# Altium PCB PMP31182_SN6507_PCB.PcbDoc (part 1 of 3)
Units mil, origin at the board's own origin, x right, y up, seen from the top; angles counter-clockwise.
Board outline 4922 x 2266 mil, 4 copper layers (Top Layer, Signal Layer 1, Signal Layer 2, Bottom Layer), stack 77.9 mil thick; 174 components, 102 nets, 540 pads, 580 vias.
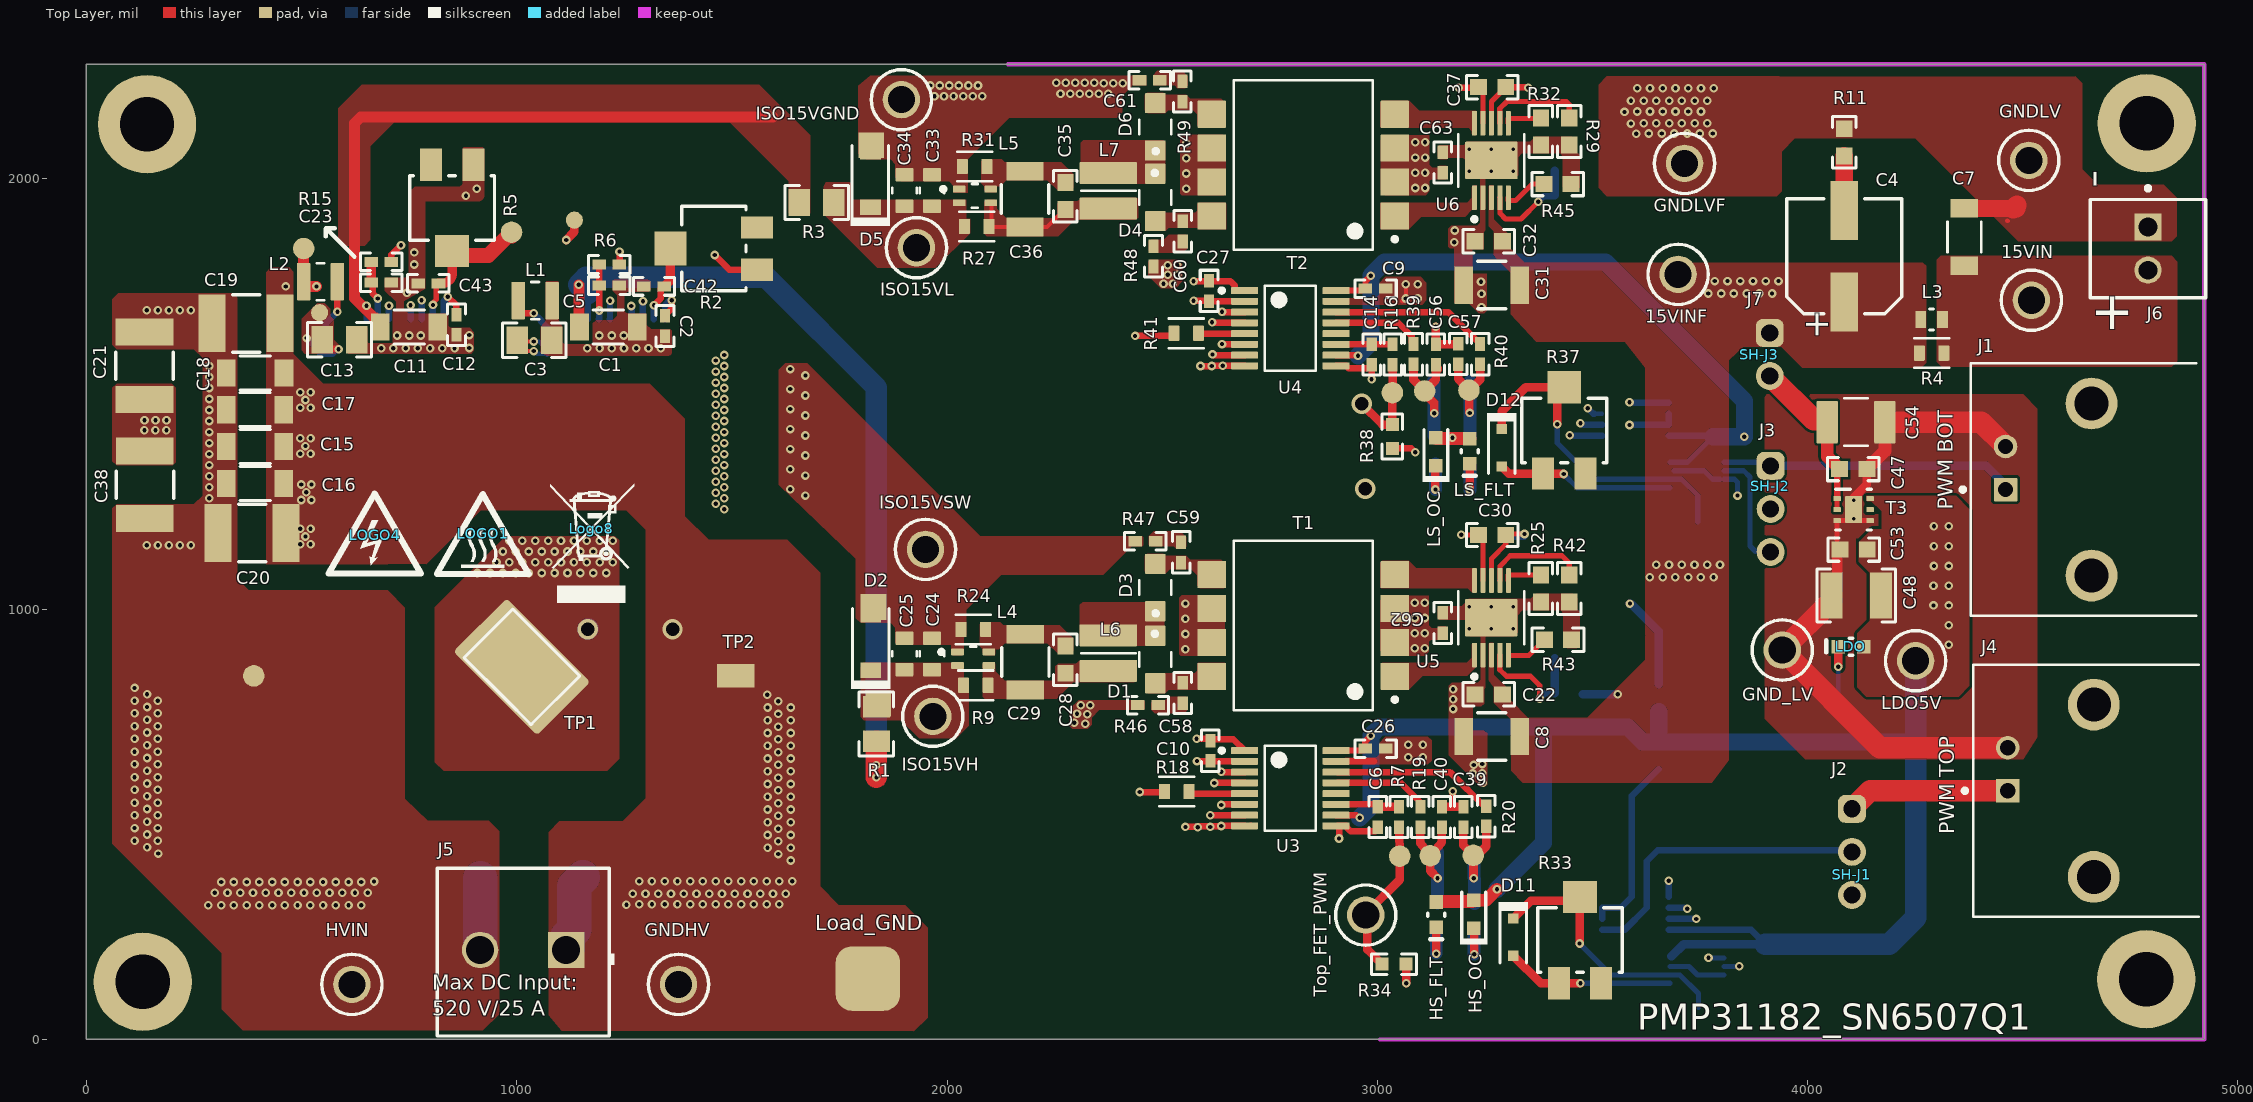
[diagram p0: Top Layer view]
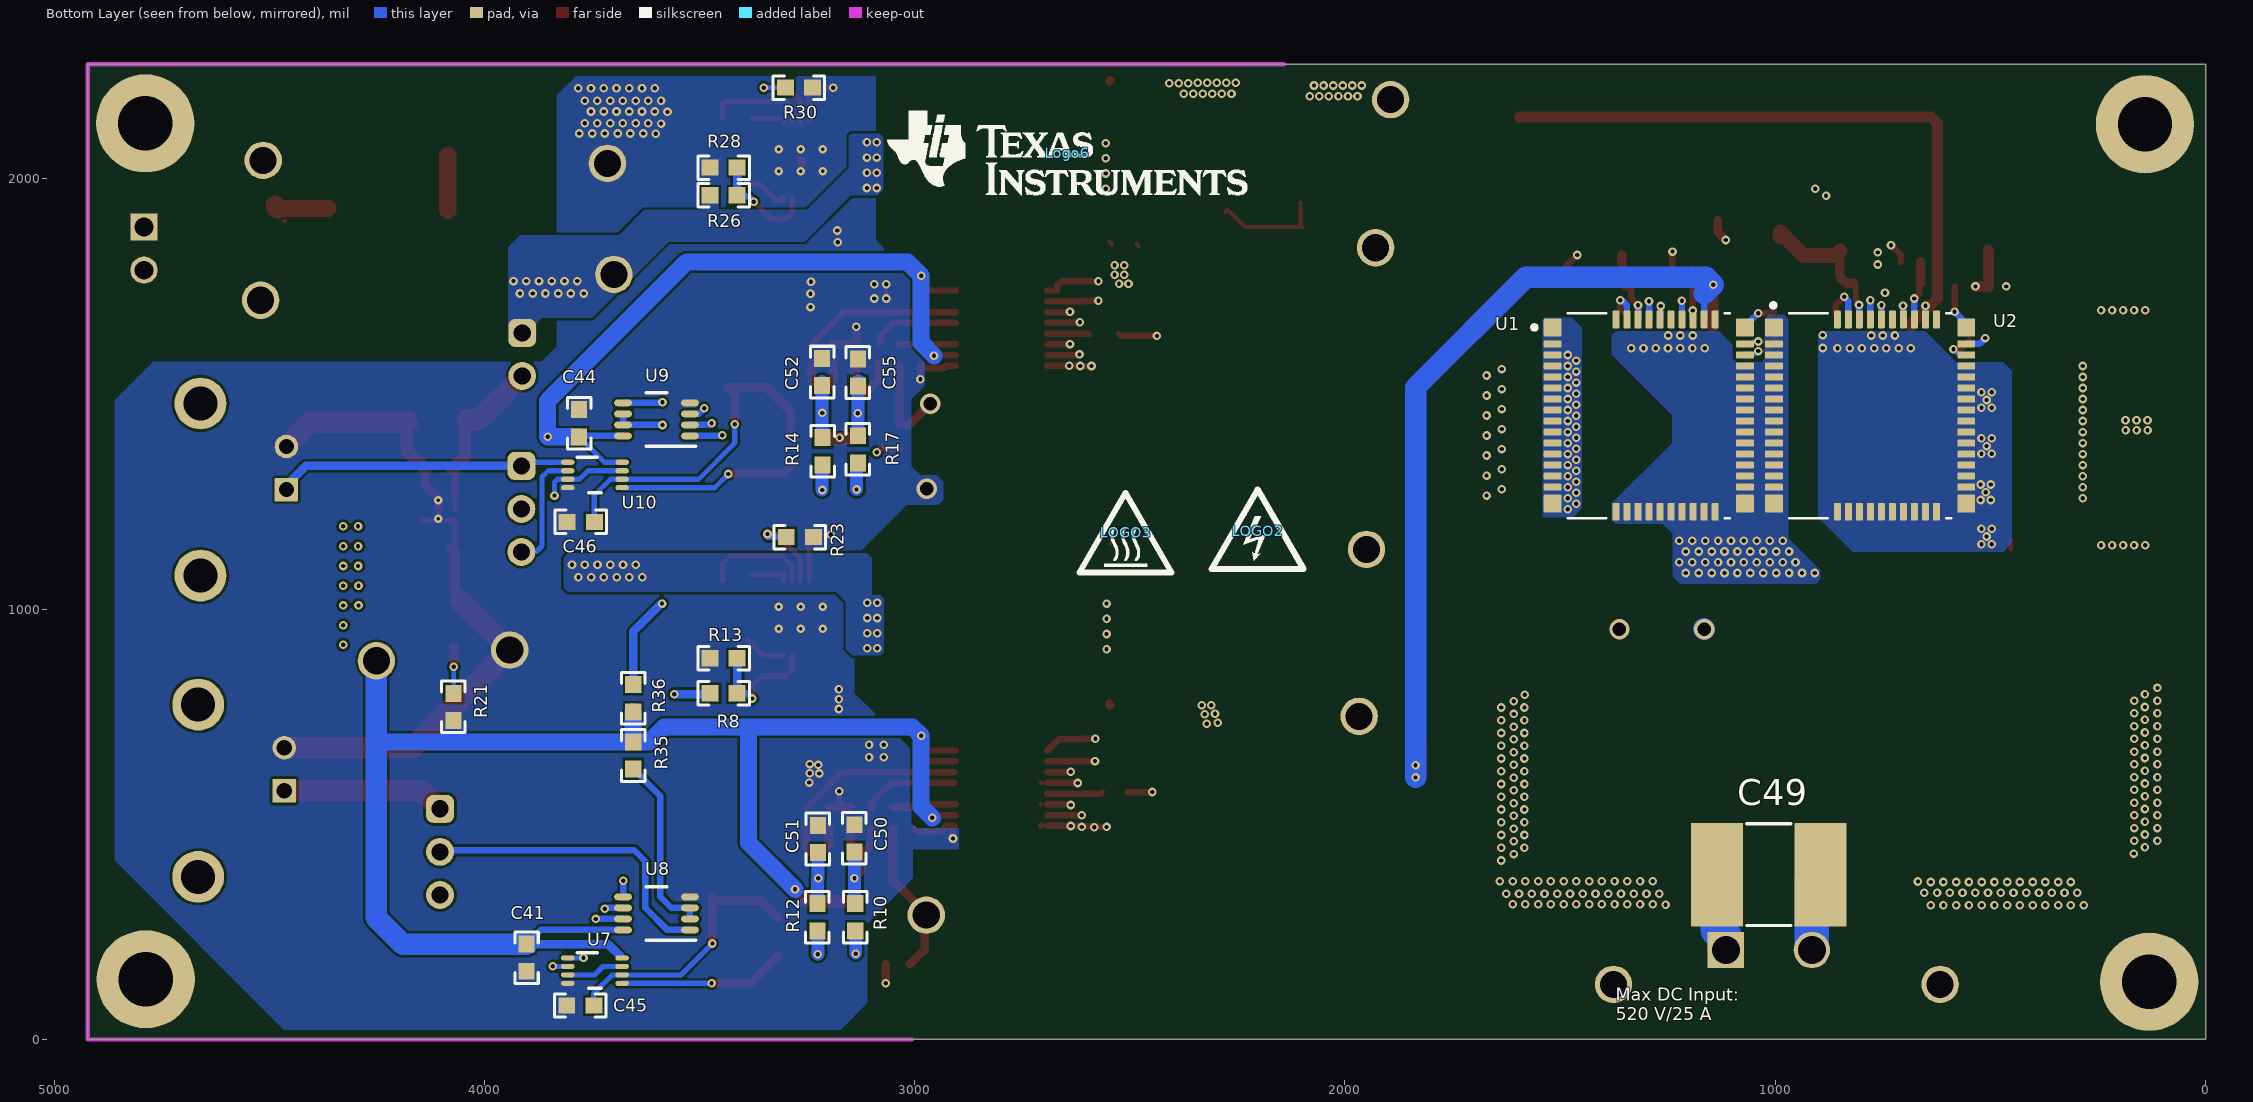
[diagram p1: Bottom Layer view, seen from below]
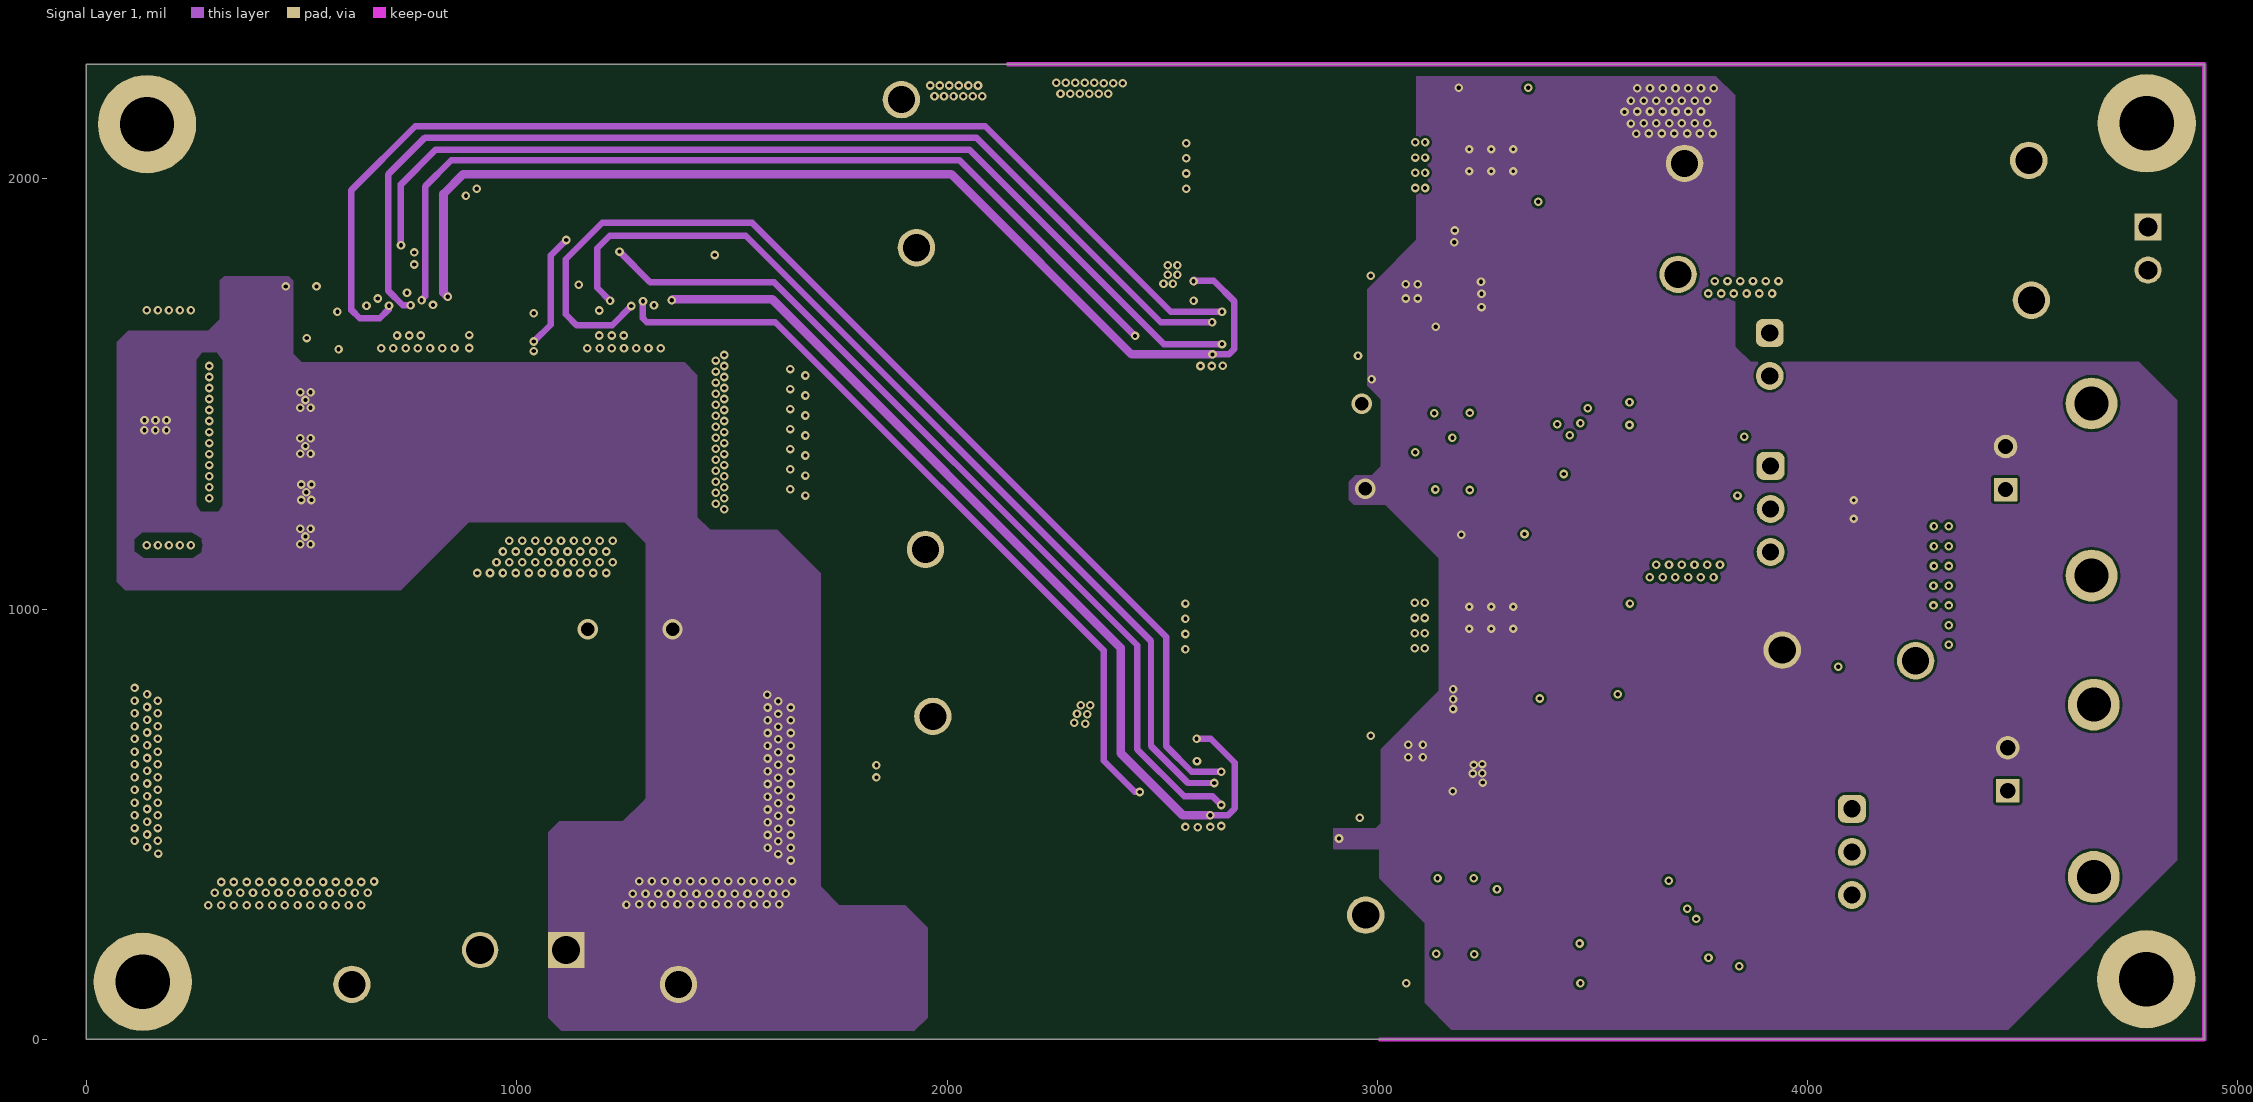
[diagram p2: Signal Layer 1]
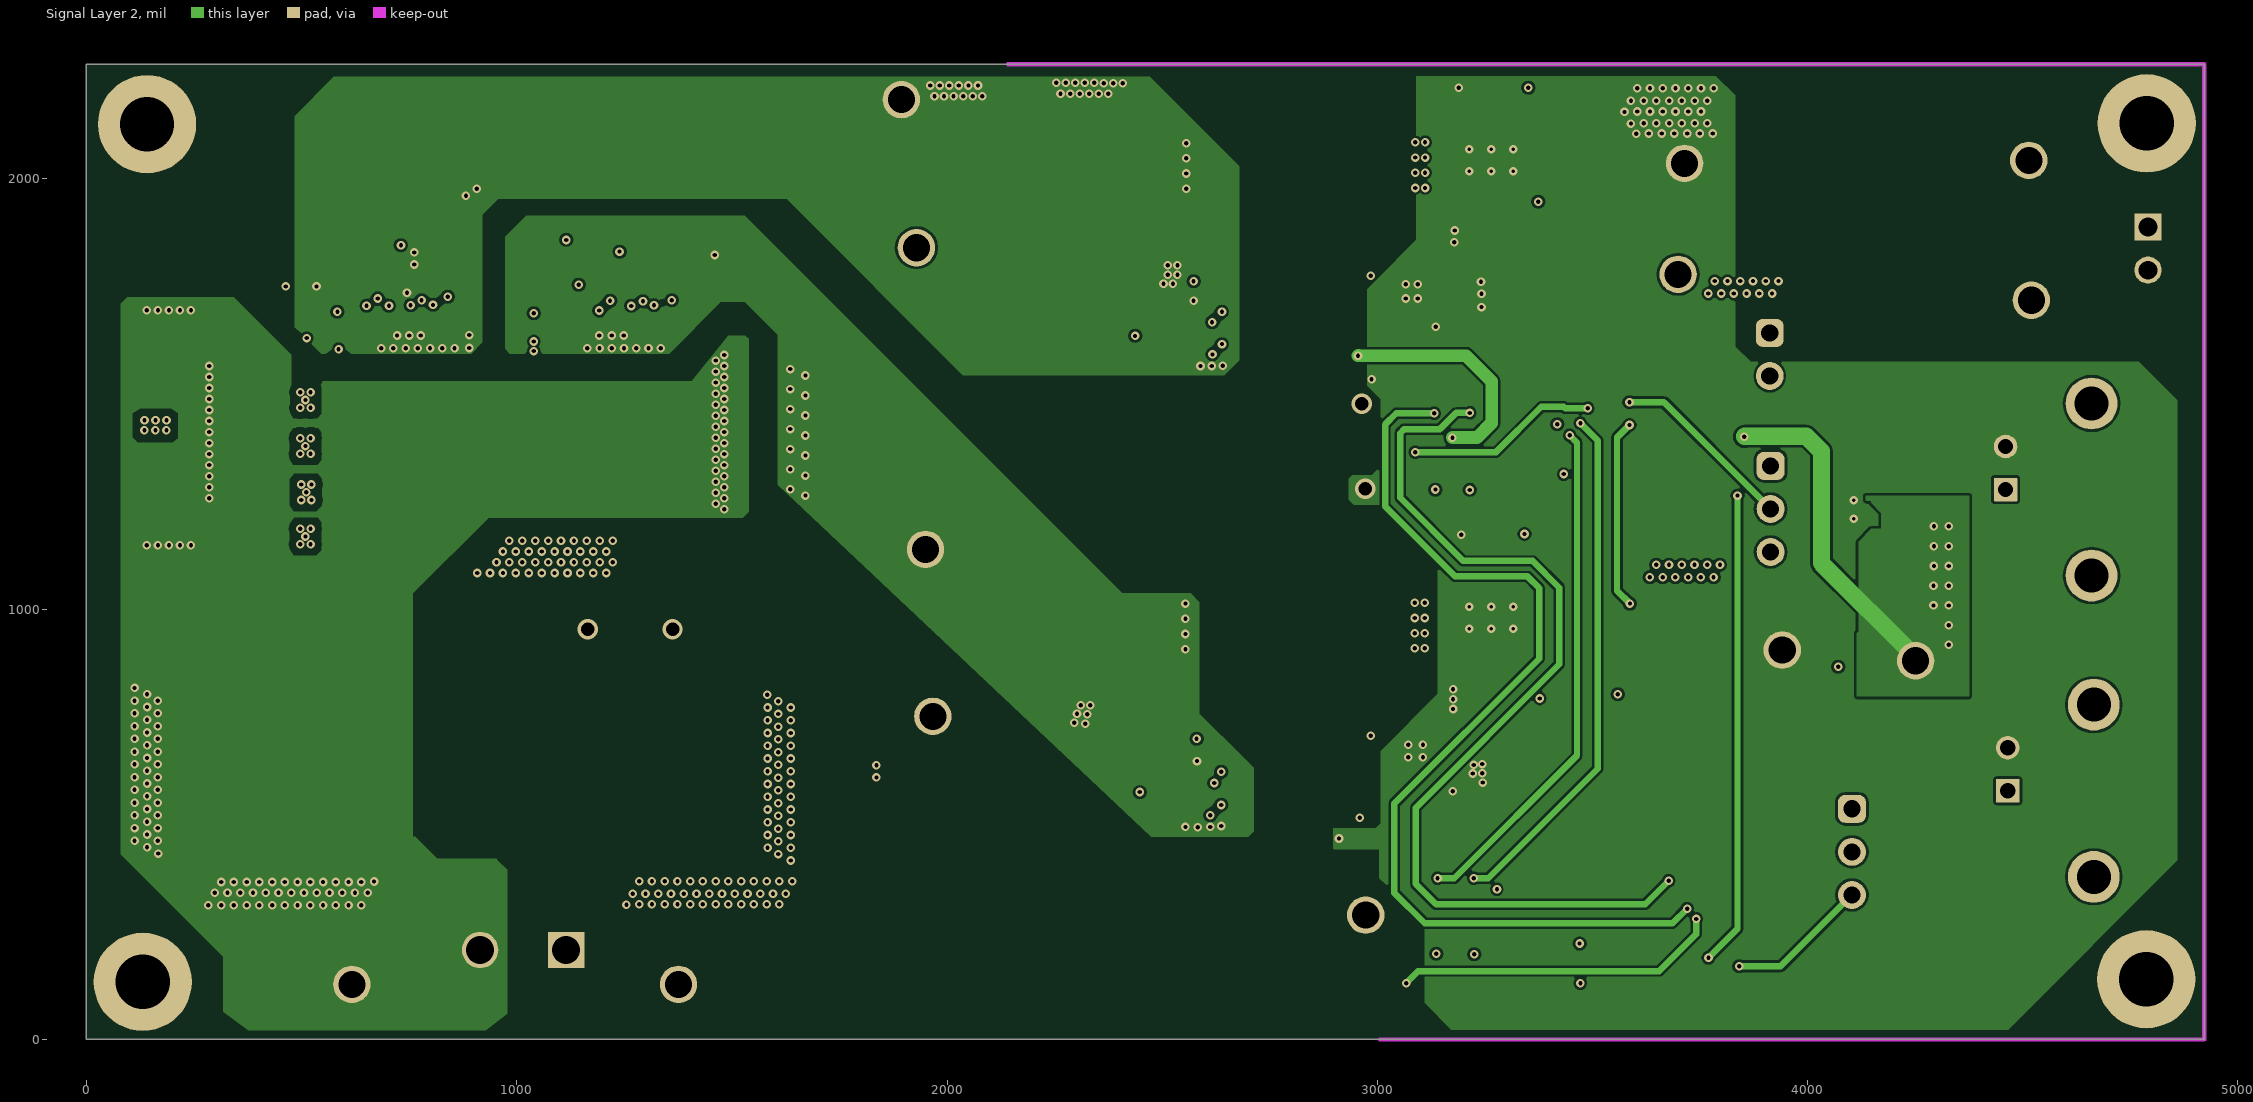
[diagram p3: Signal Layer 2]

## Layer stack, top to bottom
Top Solder: solder mask 0.4, Solder Resist, Dk 3.5
Top Layer: signal copper 2.8
Dielectric 1: prepreg 4.6, FR-4, Dk 4.2
Signal Layer 1: signal copper 2.8
Dielectric 2: core 57.5, FR-4, Dk 4.2
Signal Layer 2: signal copper 2.8
Dielectric 3: prepreg 4.6, FR-4, Dk 4.2
Bottom Layer: signal copper 2.8
Bottom Solder: solder mask 0.4, Solder Resist, Dk 3.5

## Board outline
0,2266 4922,2266 4922,0 0,0

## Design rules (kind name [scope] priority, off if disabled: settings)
AcuteAngle [All] p1: minimum=4.50000000000000E+0001 checktracksonly=FALSE
AssemblyTestPointUsage [All] p1: valid=2
BoardOutlineClearance [OnCopper] p1: gap=15 ignorepadtopadclearanceinfootprint=FALSE
Clearance "Clearance_Thermal Vias" [InNet('NC5')] p1: gap=20 ignorepadtopadclearanceinfootprint=FALSE
Clearance "Clearance_Thermal Vias_1" [InNet('NC6')] p2: gap=20 ignorepadtopadclearanceinfootprint=FALSE
Clearance Clearance_VSW_Mid1 [(OnMultiLayer Or OnMid) And InNetClass('VSWNET') vs OnMid And Not InNetClass('VSWNET')] p3: gap=16 ignorepadtopadclearanceinfootprint=TRUE
Clearance Clearance_Screw_Top [InNetClass('Screw') vs OnLayer('Top Layer') And Not InNetClass('Screw')] p4: gap=60 ignorepadtopadclearanceinfootprint=TRUE
Clearance Clearance_Screw_Bottom [InNetClass('Screw') vs OnLayer('Bottom Layer') And Not InNetClass('Screw')] p5: gap=60 ignorepadtopadclearanceinfootprint=TRUE
Clearance Clearance_Screw_Other [InNetClass('Screw') vs Not OnLayer('Top Layer')  AND Not InNetClass('Screw')] p6: gap=60 ignorepadtopadclearanceinfootprint=TRUE
Clearance Clearance_VSW_Mid2 [(OnMultiLayer Or OnMid) And Not InNetClass('VSWNET') vs OnMid And InNetClass('VSWNET')] p7: gap=16 ignorepadtopadclearanceinfootprint=TRUE
Clearance Clearance_VSW [InNetClass('VSWNET') and OnCopper vs Not InNetClass('VSWNET') and OnCopper] p8: gap=60 ignorepadtopadclearanceinfootprint=TRUE
Clearance Clearance_VHV_Mid1 [(OnMultiLayer Or OnMid) And InNetClass('VHV') vs OnMid And Not InNetClass('VHV')] p9: gap=16 ignorepadtopadclearanceinfootprint=TRUE
Clearance Clearance_VHV_Mid2 [(OnMultiLayer Or OnMid) And Not InNetClass('VHV') vs OnMid And InNetClass('VHV')] p10: gap=16 ignorepadtopadclearanceinfootprint=TRUE
Clearance Clearance_VHV [InNetClass('VHV') vs Not InNetClass('VHV')] p11: gap=60 ignorepadtopadclearanceinfootprint=FALSE
Clearance Clearance_INGND [InNetClass('INGND') and OnCopper vs Not InNetClass('INGND')  and OnCopper] p12: gap=60 ignorepadtopadclearanceinfootprint=FALSE
Clearance Clearance_Poly [All] p13: gap=6 ignorepadtopadclearanceinfootprint=FALSE
Clearance Clearance_1 [All] p14: gap=6 ignorepadtopadclearanceinfootprint=FALSE
ComponentClearance ComponentClearance_Shunt [InComponentClass('Header') vs InComponentClass('Shunt')] p1: gap=0 collisioncheckmode=3 verticalgap=0 showdistances=FALSE
ComponentClearance ComponentClearance_MountingHoles_FiducialMarks [InComponentClass('Mounting Holes') vs InComponentClass('FiducialMark')] p2 off: gap=50 collisioncheckmode=3 verticalgap=10 showdistances=FALSE
ComponentClearance ComponentClearance_Logo [InComponentClass('Logo')] p3: gap=0 collisioncheckmode=3 verticalgap=10 showdistances=FALSE
ComponentClearance ComponentClearance_ScrewToNut [(HasFootprint('NY PMS 440 0025 PH')) vs (HasFootprint('Keystone_1902C'))] p4: gap=5 collisioncheckmode=3 verticalgap=10 showdistances=FALSE
ComponentClearance ComponentClearance_MountingHoles [InComponentClass('Mounting Holes')] p5: gap=250 collisioncheckmode=3 verticalgap=100000 showdistances=FALSE
ComponentClearance ComponentClearance_SmallPassives [HasFootprint('0201*') or HasFootprint('0402*') or HasFootprint('0508') or HasFootprint('0603*') or HasFootprint('0612') or HasFootprint('0805*') or HasFootprint('0815*') or HasFootprint('0830*') or HasFootprint('1206*') or HasFootprint('1210*') or HasFootprint('1808*') or HasFootprint('1812*') or HasFootprint('1825*') or HasFootprint('2010*') or HasFootprint('2220*') or HasFootprint('2225*') or HasFootprint('2512*') or HasFootprint('2728*') or HasFootprint('3518*') vs HasFootprint('0201*') or HasFootprint('0402*') or HasFootprint('0508') or HasFootprint('0603*') or HasFootprint('0612') or HasFootprint('0805*') or HasFootprint('0815*') or HasFootprint('0830*') or HasFootprint('1206*') or HasFootprint('1210*') or HasFootprint('1808*') or HasFootprint('1812*') or HasFootprint('1825*') or HasFootprint('2010*') or HasFootprint('2220*') or HasFootprint('2225*') or HasFootprint('2512*') or HasFootprint('2728*') or HasFootprint('3518*')] p6: gap=9.84 collisioncheckmode=3 verticalgap=10 showdistances=FALSE
ComponentClearance ComponentClearance_THtoSMT [IsThruComponent vs IsSMTComponent] p7: gap=10 collisioncheckmode=3 verticalgap=30 showdistances=FALSE
ComponentClearance ComponentClearance_THtoTH [IsThruComponent vs IsThruComponent] p8: gap=74 collisioncheckmode=3 verticalgap=30 showdistances=FALSE
ComponentClearance [All] p9: gap=1 collisioncheckmode=3 verticalgap=10 showdistances=FALSE
DiffPairsRouting [All] p1: maxlimit=100 minlimit=10 mostfreqgap=10 toplayer_minwidth=15 toplayer_maxwidth=15 toplayer_prefwidth=15 midlayer1_minwidth=15 midlayer1_maxwidth=15 midlayer1_prefwidth=15 midlayer2_minwidth=15 midlayer2_maxwidth=15 midlayer2_prefwidth=15 bottomlayer_minwidth=15 bottomlayer_maxwidth=15 bottomlayer_prefwidth=15 maxuncoupledlength=1000
FabricationTestPointUsage TestPointUsage [All] p1: valid=2 allowmultiple=FALSE
FabricationTestpoint Testpoint [All] p1: side=3 testpointundercomponent=TRUE minsize=40 maxsize=100 preferedsize=60 minholesize=0 maxholesize=40 preferedholesize=32 testpointgrid=1 allowsidetop=TRUE allowsidebottom=TRUE usegrid=TRUE gridtolerance=0.01
FanoutControl Fanout_LCC [IsLCC] p1: bgadir=Out bgaviamode=Centered fanoutstyle=Auto fanoutdirection=Alternating viagrid=1 // Fanout_LCC (Default Rule)
FanoutControl Fanout_BGA [IsBGA] p2: bgadir=Out bgaviamode=Centered fanoutstyle=Auto fanoutdirection=Alternating viagrid=1 // Fanout_BGA (Default Rule)
FanoutControl Fanout_Default [All] p4: bgadir=Out bgaviamode=Centered fanoutstyle=Auto fanoutdirection=Alternating viagrid=1 // Fanout_Default (Default Rule)
FanoutControl Fanout_Small [(CompPinCount < 5)] p5: bgadir=Out bgaviamode=Centered fanoutstyle=Auto fanoutdirection=OutThenIn viagrid=1 // Fanout_Small (Default Rule)
HoleSize [All] p1: absolutevalues=TRUE maxlimit=251 minlimit=6 maxpercent=80.000 minpercent=20.000
MinimumAnnularRing MinimumAnnularRing_ThermalPadVias [IsVia and InAnyComponent] p1: minimumring=4.5
MinimumAnnularRing [IsVia] p2: minimumring=4.5
MinimumSolderMaskSliver MinimumSolderMaskSliver_Logo [InComponentClass('Logo') vs InComponentClass('Logo')] p1: minsoldermaskwidth=0.7
MinimumSolderMaskSliver [All] p2: minsoldermaskwidth=3.94
PlaneConnect [All] p1: planeconnectstyle=Relief reliefexpansion=10 reliefentries=4 reliefconductorwidth=10 reliefairgap=10
PolygonConnect [All] p1: connectstyle=Direct reliefconductorwidth=10 reliefentries=4 polygonreliefangle="90 Angle" airgapwidth=10
RoutingVias ThermalPadVias [IsVia and InAnyComponent] p1: holewidth=7.87 width=19.68 viastyle="Through Hole" minholewidth=7.87 minwidth=19.68 maxholewidth=12.99 maxwidth=23.62
RoutingVias [All] p2: holewidth=10 width=20 viastyle="Through Hole" minholewidth=6 minwidth=10 maxholewidth=40 maxwidth=65
SMDToCorner [All] p1: distance=30000
SilkToSilkClearance [All] p1: silktosilkclearance=0
SilkToSolderMaskClearance SilkscreenOverComponentPads [IsPad] p1: minsilkscreentomaskgap=5 clearancetoexposedcopper=TRUE
SolderMaskExpansion [All] p1: expansion=1.97 istentingtop=FALSE
Width [All] p1: maxlimit=1000 minlimit=6 preferedwidth=10 checkconnectedcopper=TRUE
16 further rules are at their usual default settings.

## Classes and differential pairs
component class Shunt: SH-J1 SH-J2 SH-J3
component class PMP31182_SN6507_PWM: C41 C44 C45 C46 C47 C48 C49 C50 C51 C52 C53 C54 C55 D11 D12 GND_LV GNDHV HS_FLT HS_OC HVIN J1 J2 J3 J4 J5 J7 LDO LDO5V LS_FLT LS_OC R10 R12 R14 R17 R21 R33 R34 R35 R36 R37 R38 SH-J1 SH-J2 SH-J3 T3 Top_FET_PWM U7 U8 U9 U10
component class PMP31182_SN6507_power_supply: 15VIN 15VINF 30 C4 C7 C8 C22 C24 C25 C28 C29 C30 C31 C32 C33 C34 C35 C36 C37 C58 C59 C60 C61 C62 C63 D1 D2 D3 D4 D5 D6 GNDLV GNDLVF ISO15VGND ISO15VH ISO15VL ISO15VSW J6 L3 L4 L5 L6 L7 R4 R8 R9 R11 R13 R23 R24 R25 R26 R27 R28 R29 R30 R31 R32 R42 R43 R45 R46 R47 R48 R49 T1 T2 U5 U6
component class Logo: Logo6
component class Header: J2 J3 J7
net class PGND: 5V_L FAULT_L GND_HV IN_L ISO_15V_L NC_PGND1 NC_PGND2 NC_PGND3 NetC11_2 NetC43_2 NetL2_2 NetR15_1 NetR41_2 OC_L TEMP_L VNEG_L
component class PMP31182_SN6507_Hardware: !PCB1 FID2 H3 H4 H5 H6 LOGO1 LOGO2 LOGO3 LOGO4 Logo6 Logo8
component class PMP31182_SN6507_GaN: C1 C2 C3 C5 C6 C9 C10 C11 C12 C13 C14 C15 C16 C17 C18 C19 C20 C21 C23 C26 C27 C38 C39 C40 C42 C43 C56 C57 L1 L2 R1 R2 R3 R5 R6 R7 R15 R16 R18 R19 R20 R39 R40 R41 TP1 TP2 U1 U2 U3 U4
net class VSWNET: 5V_H FAULT_H IN_H ISO_15V_H ISO_15V_H_B ISO_RET_H_B NC_SW1 NC_SW2 NC_SW3 NetC1_1 NetC42_1 NetC58_1 NetC58_2 NetC59_1 NetC59_2 NetD1_1 NetL1_2 NetR6_1 NetR18_1 OC_H SW TEMP_H VNEG_H
net class VHV: HVBUS

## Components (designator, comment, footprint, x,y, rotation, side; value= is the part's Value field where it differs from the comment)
15VIN "5005" Keystone5005 4520,1718 r180 top
15VINF "5005" Keystone5005 3699,1778 r180 top
C1 "TMK316AB7106KLHT" 1206_180 1213,1656 r0 top value=10uF
C2 "GCM155R71C224KE02D" 0402 1344.59,1658 r270 top value=0.22uF
C3 "CGA4J3X7R1E225K125AB" 0805_HV 1041,1625 r180 top value=2.2uF
C4 "HHXC250ARA470MF61G" HXB_F61 4085,1820 r90 top value=47uF
C5 "GCM1555C1H220JA16D" 0402 1215,1752 r180 top value=22pF
C6 "C1005C0G1H680J050BA" 0402 3001,517.12 r270 top value=68pF
C7 "C1206C106J3RACAUTO" 1206_180 4364,1865 r90 top value=10uF
C8 "CGA6P3X7R1H475M250AB" 1210_280 3266,704 r180 top value=4.7uF
C9 "GRT155R6YA105KE13D" 0402 2996,1744.81 r0 top value=1uF
C10 "GCM155R71H104KE02D" 0402 2612,671 r270 top value=0.1uF
C11 "TMK316AB7106KLHT" 1206_180 749.96,1656 r180 top value=10uF
C12 "GCM155R71C224KE02D" 0402 860,1661 r270 top value=0.22uF
C13 "CGA4J3X7R1E225K125AB" 0805_HV 588,1626 r180 top value=2.2uF
C14 "C1005C0G1H680J050BA" 0402 2987,1591.88 r90 top value=68pF
C15 "C1206C223KDRACTU" 1206_190 392,1378 r0 top value=0.022uF
C16 "C1206C223KDRACTU" 1206_190 392,1292 r0 top value=0.022uF
C17 "C1206C223KDRACTU" 1206_190 391.87,1463.49 r0 top value=0.022uF
C18 "C1206C223KDRACTU" 1206_190 392.15,1549.1 r0 top value=0.022uF
C19 "C1812W104KDRACTU" 1812_254 371,1664 r0 top value=0.1uF
C20 "C1812W104KDRACTU" 1812_254 385,1177 r0 top value=0.1uF
C21 "C1812W104KDRACTU" 1812_254 135,1565.74 r270 top value=0.1uF
C22 "CGA3E3X8R1H104K080AE" 0603 3259,802 r180 top value=0.1uF
C23 "GCM1555C1H220JA16D" 0402 685.1,1758.91 r180 top value=22pF
C24 "CGA4J1X7S1E106K125AC" FP-CGA4J1X7S1E106K125AC_0805-MFG 1965,896 r90 top value=10µF
C25 "CGA4J1X7S1E106K125AC" FP-CGA4J1X7S1E106K125AC_0805-MFG 1901,896 r90 top value=10µF
C26 "GRT155R6YA105KE13D" 0402 2996,676 r0 top value=1uF
C27 "GCM155R71H104KE02D" 0402 2609,1739.62 r270 top value=0.1uF
C28 "CGA3E3X8R1H104K080AE" 0603 2275,882.5 r90 top value=0.1uF
C29 "CGA6P1X7R1E106M250AC" 1210_280 2182,877 r90 top value=10uF
C30 "GCM188R71E105KA64D" 0603 3267,1172.4 r180 top value=1uF
C31 "CGA6P3X7R1H475M250AB" 1210_280 3266,1753 r180 top value=4.7uF
C32 "CGA3E3X8R1H104K080AE" 0603 3259,1855 r180 top value=0.1uF
C33 "CGA4J1X7S1E106K125AC" FP-CGA4J1X7S1E106K125AC_0805-MFG 1965,1973 r90 top value=10µF
C34 "CGA4J1X7S1E106K125AC" FP-CGA4J1X7S1E106K125AC_0805-MFG 1901,1973 r90 top value=10µF
C35 "CGA3E3X8R1H104K080AE" 0603 2275,1960 r90 top value=0.1uF
C36 "CGA6P1X7R1E106M250AC" 1210_280 2181,1953 r90 top value=10uF
C37 "GCM188R71E105KA64D" 0603 3267,2213 r180 top value=1uF
C38 "C1812W104KDRACTU" 1812_254 136,1289 r90 top value=0.1uF
C39 "GCQ1555C1H430JB01D" 0402 3200,517 r90 top value=43pF
C40 "GCQ1555C1H430JB01D" 0402 3150,517 r90 top value=43pF
C41 "CGA3E1X7R1E105K080AD" 0603 3902,190 r90 bottom value=1uF
C42 "CGA2B2C0G1H101J050BA" 0402 1319,1750 r180 top value=100pF
C43 "CGA2B2C0G1H101J050BA" 0402 794.62,1757 r0 top value=100pF
C44 "CGA3E1X7R1E105K080AD" 0603 3780,1432 r270 bottom value=1uF
C45 "GRM1885C1H390JA01D" 0603 3777,79 r0 bottom value=39pF
C46 "GRM1885C1H390JA01D" 0603 3776,1203 r0 bottom value=39pF
C47 "CGA3E3X8R1H104K080AE" 0603 4106,1325.63 r0 top value=0.1uF
C48 "GRT32ER61E226KE13L" 1210_270 4113,1031.63 r180 top value=22uF
C49 "2220Y6300105KETWS2" 2220_450 1015,383 r0 bottom value=1uF
C50 "GRM1885C1H390JA01D" 0603 3140,467.5 r90 bottom value=39pF
C51 "GRM1885C1H390JA01D" 0603 3225,466 r90 bottom value=39pF
C52 "GRM1885C1H390JA01D" 0603 3214.93,1551 r90 bottom value=39pF
C53 "CGA3E3X8R1H104K080AE" 0603 4107,1138.63 r180 top value=0.1uF
C54 "UMK325AB7106KMHP" FP-UMK325AB7106KMHP_1210-MFG 4112.43,1434.63 r180 top value=10µF
C55 "GRM1885C1H390JA01D" 0603 3131.93,1550 r90 bottom value=39pF
C56 "GCQ1555C1H430JB01D" 0402 3136,1592 r90 top value=43pF
C57 "GCQ1555C1H430JB01D" 0402 3188,1593 r90 top value=43pF
C58 "GRM1555C1H620JA01D" 0402 2548,805 r270 top value=62pF
C59 "GRM1555C1H620JA01D" 0402 2544,1132 r90 top value=62pF
C60 "GRM1555C1H620JA01D" 0402 2548,1878 r270 top value=62pF
C61 "GRM1555C1H620JA01D" 0402 2547,2203 r90 top value=62pF
C62 "C1005X6S1H104K050BB" 0402 3152,968 r90 top value=0.1uF
C63 "C1005X6S1H104K050BB" 0402 3152,2038 r90 top value=0.1uF
D1 "PMEG200G20ELRX" FP-PMEG6020ELRX_SOD123W-MFG 2484,883 r270 top
D2 "BZT52C18-7-F" SOD-123 1823,922 r90 top value=18V
D3 "PMEG200G20ELRX" FP-PMEG6020ELRX_SOD123W-MFG 2484,1050 r90 top
D4 "PMEG200G20ELRX" FP-PMEG6020ELRX_SOD123W-MFG 2484,1957 r270 top
D5 "BZT52C18-7-F" SOD-123 1822,1998 r90 top value=18V
D6 "PMEG200G20ELRX" FP-PMEG6020ELRX_SOD123W-MFG 2484,2121 r90 top
D11 "BAT42WS-7-F" SOD-323 3316,238 r270 top value=30V
D12 "BAT42WS-7-F" SOD-323 3289,1375 r270 top value=30V
GND_LV "5006" Keystone5006 3941,905 r180 top
GNDHV "5006" Keystone5006 1376,128 r180 top
GNDLV "5006" Keystone5006 4514,2043 r180 top
GNDLVF "5006" Keystone5006 3714,2036 r180 top
HS_FLT "LS L29K-G1J2-1-Z" "LS L29K_Red" 3137,290 r270 top value=Red
HS_OC "SML-E12Y8WT86" SML-E1_Yellow 3224,291 r90 top value=Yellow
HVIN "5005" Keystone5005 617,128 r0 top
ISO15VGND "5006" Keystone5006 1894,2184 r180 top
ISO15VH "5005" Keystone5005 1967,751 r180 top
ISO15VL "5005" Keystone5005 1929,1840 r180 top
ISO15VSW "5006" Keystone5006 1950,1139 r180 top
J1 "0731375003" FP-0731375003_CONN_BNC_RCPT-MFG 5074.57,1278 r90 top
J2 "TSW-103-07-G-S" TSW-103-07-G-S 4103,436 r270 top
J3 "TSW-103-07-G-S" TSW-103-07-G-S 3914,1233 r270 top
J4 "0731375003" FP-0731375003_CONN_BNC_RCPT-MFG 5079.57,578 r90 top
J5 "0395443002" Molex_0395443002 1015,208 r180 top
J6 "282834-2" TEC_282834-2 4791,1838 r270 top
J7 "TSW-102-07-G-S" TSW-102-07-G-S 3912,1592 r270 top
L1 "MPIA2510V2-4R7-R" FP-MPIA2510V2-4R7-R_1008-MFG 1043,1717 r180 top value=4.7uH
L2 "MPIA2510V2-4R7-R" FP-MPIA2510V2-4R7-R_1008-MFG 544,1761 r0 top value=4.7uH
L3 "0603PS-SRF Inductor" 0603AF 4288,1673 r180 top value=240nH
L4 "ACM2012-900-2P-T001" FP-ACM2012-900-2P-T001_SMD4-MFG 2060.92,884.75 r0 top
L5 "ACM2012-900-2P-T001" FP-ACM2012-900-2P-T001_SMD4-MFG 2065,1960.44 r0 top
L6 "74438335330" FP-74438335330_SMT2_3MM0_3MM0-MFG 2375,898 r270 top value=33uH
L7 "74438335330" FP-74438335330_SMT2_3MM0_3MM0-MFG 2375,1972 r270 top value=33uH
LDO "LS L29K-G1J2-1-Z" "LS L29K_Red" 4100.53,913 r180 top value=Red
LDO5V "5005" Keystone5005 4251,880 r180 top
LOGO1 "CAUTION HOT SURFACE" IEC_HotSurface_Small 921.25,1174.75 r0 top
LOGO2 "DANGER HIGH VOLTAGE" IEC_HighVoltage_Small 2203,1181 r180 bottom
LOGO3 "CAUTION HOT SURFACE" IEC_HotSurface_Small 2510,1178 r180 bottom
LOGO4 "DANGER HIGH VOLTAGE" IEC_HighVoltage_Small 670,1171.25 r0 top
Logo6 "Texas Instruments" TI_Stacked_Overlay_Small 2645,2060 r180 bottom
Logo8 "WEEE logo" WEEE_Minimum 1173.5,1187 r0 top
LS_FLT "LS L29K-G1J2-1-Z" "LS L29K_Red" 3215,1367 r270 top value=Red
LS_OC "SML-E12Y8WT86" SML-E1_Yellow 3136,1366 r90 top value=Yellow
R1 "CRCW08050000Z0EAHP" 0805_HV 1836,733 r270 top value=0
R2 "3224X-1-204E" TRIM_3224X 1458,1838 r180 top value=200K
R3 "CRCW08050000Z0EAHP" 0805_HV 1697,1945 r180 top value=0
R4 "ERJ-3GEY0R00V" FP-ERJ-3GEY0R00V_0603-MFG 4288,1595 r180 top
R5 "3224X-1-204E" TRIM_3224X 850,1932.39 r270 top value=200K
R6 "CRCW0402300RJNED" 0402 1215,1801 r180 top value=300
R7 "CRCW040249R9FKED" 0402 3050.5,517.12 r90 top value=49.9
R8 "RT0603BRD076K81L" 0603 3444,804.55 r0 bottom value=6.81k
R9 "ERJ-3GEY0R00V" FP-ERJ-3GEY0R00V_0603-MFG 2067,823 r180 top
R10 "CRCW06033K30JNEA" 0603 3138,284 r270 bottom value=3.3k
R11 "ERJ-3RQFR33V" 0603 4085,2085 r270 top value=0.33
R12 "CRCW06033K30JNEA" 0603 3226,284 r270 bottom value=3.3k
R13 "RT0603BRD071KL" 0603 3444,886 r180 bottom value=1.00k
R14 "CRCW06033K30JNEA" 0603 3214.07,1367 r270 bottom value=3.3k
R15 "CRCW0402300RJNED" 0402 685.1,1807 r180 top value=300
R16 "CRCW040249R9FKED" 0402 3035.5,1591.88 r90 top value=49.9
R17 "CRCW06033K30JNEA" 0603 3132,1371.5 r270 bottom value=3.3k
R18 "ERJ-3GEY0R00V" FP-ERJ-3GEY0R00V_0603-MFG 2534,576 r180 top
R19 "CRCW0402300RJNED" 0402 3100,517 r270 top value=300
R20 "CRCW0402300RJNED" 0402 3253,518.62 r270 top value=300
R21 "CRCW06033K30JNEA" 0603 4072,773 r90 bottom value=3.3k
R23 "RT0603BRD0750K5L" 0603 3267,1167.4 r0 bottom value=50.5k
R24 "ERJ-3GEY0R00V" FP-ERJ-3GEY0R00V_0603-MFG 2061,953 r180 top
R25 "" 0603 3380,1048 r90 top value=1.00k
R26 "RT0603BRD076K81L" 0603 3444,1962 r0 bottom value=6.81k
R27 "ERJ-3GEY0R00V" FP-ERJ-3GEY0R00V_0603-MFG 2069,1889.44 r180 top
R28 "RT0603BRD071KL" 0603 3444,2026 r180 bottom value=1.00k
R29 "RC0603FR-0721KL" 0603 3446,2110 r90 top value=21.0k
R30 "RT0603BRD0750K5L" 0603 3269,2212 r0 bottom value=50.5k
R31 "ERJ-3GEY0R00V" FP-ERJ-3GEY0R00V_0603-MFG 2064,2028.44 r180 top
R32 "" 0603 3380,2110 r90 top value=1.00k
R33 "3224X-1-502E" TRIM_3224X 3471,231 r90 top value=5K
R34 "CRCW06030000Z0EA" 0603_HV 3039,175 r180 top value=0
R35 "CRCW0603100KJNEAC" 0603 3654,660 r270 bottom value=100k
R36 "CRCW0603100KJNEAC" 0603 3654,793 r270 bottom value=100k
R37 "3224X-1-502E" TRIM_3224X 3434.5,1415.5 r90 top value=5K
R38 "CRCW06030000Z0EA" 0603_HV 3035,1401 r90 top value=0
R39 "CRCW0402300RJNED" 0402 3084,1592.62 r270 top value=300
R40 "CRCW0402300RJNED" 0402 3239,1592.62 r270 top value=300
R41 "ERJ-3GEY0R00V" FP-ERJ-3GEY0R00V_0603-MFG 2556,1641 r180 top
R42 "RC0603FR-0721KL" 0603 3446,1048 r90 top value=21.0k
R43 "RT0603BRD07106KL" 0603 3420,929 r180 top value=106k
R45 "RT0603BRD07106KL" 0603 3419,1988 r180 top value=106k
R46 "RMCF0402JT100R" 0402 2467,777 r0 top value=100
R47 "RMCF0402JT100R" 0402 2461,1158 r0 top value=100
R48 "RMCF0402JT100R" 0402 2480,1820 r90 top value=100
R49 "RMCF0402JT100R" 0402 2471,2229 r0 top value=100
SH-J1 "SNT-100-BK-G" SNT-100-BK-G 4103,383 r270 top value=1x2
SH-J2 "SNT-100-BK-G" SNT-100-BK-G 3913,1286 r270 top value=1x2
SH-J3 "SNT-100-BK-G" SNT-100-BK-G 3888,1591 r90 top value=1x2
T1 "ZD2113-AE" FP-TX1-ZB1459-BED_SMT8_8MM1_10MM0-MFG 2828,962 r180 top
T2 "ZD2113-AE" FP-TX1-ZB1459-BED_SMT8_8MM1_10MM0-MFG 2828,2032 r180 top
T3 "TPS7B8150QDRVRQ1" DRV0006A 4107,1231.35 r0 top
Top_FET_PWM "5007" Keystone5007 2973,289 r90 top
TP1 "5016" Testpoint_Keystone_Compact 1012,866 r135 top
TP2 "S2751-46R" Harwin_S2751-46R 1509,845 r180 top
U1 "LMG3525R030Q" RQS0052A-MFG 1294,1449.98 r180 bottom
U2 "LMG3525R030Q" RQS0052A-MFG 779.58,1449.98 r180 bottom
U3 "ISO7741FQDBQRQ1" DBQ0016A-MFG 2797.78,584 r0 top
U4 "ISO7741FQDBQRQ1" DBQ0016A-MFG 2797.78,1653 r0 top
U5 "SN6507DGQR" DGQ0010D-C01-MFG 3265,980 r90 top
U6 "SN6507DGQR" DGQ0010D-C01-MFG 3265,2043 r90 top
U7 "SN74LVC3G14DCUTG4" DCU0008A_N 3743.01,160 r180 bottom
U8 "SN74LVC2G08IDCTRQ1" DCT0008A_N 3600,293 r0 bottom
U9 "SN74LVC2G08IDCTRQ1" DCT0008A_N 3600,1441 r0 bottom
U10 "SN74LVC3G14DCUTG4" DCU0008A_N 3743.01,1311.84 r180 bottom

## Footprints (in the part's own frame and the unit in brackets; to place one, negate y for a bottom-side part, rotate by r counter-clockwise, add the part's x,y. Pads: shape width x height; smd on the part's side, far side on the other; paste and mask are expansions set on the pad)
0402 [mm] "0402 from SM-752 data"
  rect 0.8x0.6 smd: 1(-0.6,0) 2(0.6,0)
  silkscreen extent -1.22,-0.52 1.22,0.52, body extent -0.55,-0.3 0.55,0.3, height 0.6
0603 [mm] "0603 from SM-752 data"
  rect 1x0.95 smd: 1(-0.8,0) 2(0.8,0)
  silkscreen extent -1.52,-0.69 1.52,0.69, body extent -0.87,-0.47 0.87,0.47, height 1
0603_HV [mil] "Ernesto recommended land pattern.  26 mil between pads."
  rect 30x30 smd: 1(-28,0) 2(28,0)
  silkscreen extent -52,-24 52,24, body extent -34,-19 34,19, height 39
0603AF [mm] "COILCRAFT"
  rect 0.64x1.02 smd: 1(-0.64,0) 2(0.64,0)
  silkscreen extent -0.13,-0.63 0.13,0.63, body extent -0.92,-0.56 0.92,0.56, height 0.9
0805_HV [mil] "0805 with 30mil clearance between pads"
  rect 50x63 smd: 1(-40,0) 2(40,0)
  silkscreen extent -74,-40 74,40, body extent -43,-29 43,29, height 57
1206_180 [mm] "1206_180"
  rect 1.1x1.6 smd: 1(-1.7,0) 2(1.7,0)
  silkscreen extent -0.9,-1 0.9,1, body extent -1.75,-0.95 1.75,0.95, height 1.8
1206_190 [mm] "1206_190"
  rect 1.1x1.6 smd: 1(-1.7,0) 2(1.7,0)
  silkscreen extent -0.9,-1 0.9,1, body extent -1.75,-0.95 1.75,0.95, height 1.9
1210_270 [mm] "1210"
  rect 1.3x2.7 smd: 1(-1.45,0) 2(1.45,0)
  silkscreen extent -2.32,-1.57 2.32,1.57, body extent -1.7,-1.35 1.7,1.35, height 2.7
1210_280 [mm] "SMD, 2-Leads, Body 3.6x2.8mm, Height 2.8mm"
  rect 1.1x2.2 smd: 1(-1.65,0) 2(1.65,0)
  silkscreen extent -0.84,-1.4 0.84,1.4, body extent -1.8,-1.4 1.8,1.4, height 2.8
1812_254 [mm] "SMD, 2-Leads, Body 4.8x3.4mm"
  rect 1.6x3.4 smd: 1(-2,0) 2(2,0)
  silkscreen extent -0.8,-1.7 0.8,1.7, body extent -2.4,-1.7 2.4,1.7, height 2.54
2220_450 [mm] "Laird recommended land pattern"
  rrect3% 3.07x6.1 smd: 1(-3.06,0) 2(3.06,0)
  silkscreen extent -1.3,-3 1.3,3, body extent -2.8,-2.54 2.79,2.54, height 4.5
DBQ0016A-MFG [mm]
  rrect24% 1.6x0.41 smd paste+0 mask+0: 1(-2.7,2.222) 2(-2.7,1.587) 3(-2.7,0.953) 4(-2.7,0.318) 5(-2.7,-0.318) 6(-2.7,-0.953) 7(-2.7,-1.588) 8(-2.7,-2.223) 9(2.7,-2.223) 10(2.7,-1.588) 11(2.7,-0.953) 12(2.7,-0.318) 13(2.7,0.318) 14(2.7,0.953) 15(2.7,1.587) 16(2.7,2.222)
  silkscreen extent -4.17,-2.5 1.5,2.5, body extent -3.6,-2.75 3.6,2.75, height 0.25
DCT0008A_N [mm] "TSOP, 8-Leads, Body 3x2.8mm, Pitch 0.65mm, IPC Medium Density"
  oval 1.05x0.4 smd: 1(-1.975,0.975) 2(-1.975,0.325) 3(-1.975,-0.325) 4(-1.975,-0.975) 5(1.975,-0.975) 6(1.975,-0.325) 7(1.975,0.325) 8(1.975,0.975)
  silkscreen extent -2.32,-1.57 0.6,1.58, body extent -2.01,-1.47 2.01,1.48, height 1.3
DCU0008A_N [mm] "TSSOP, 8-Leads, Body 2x2.3mm, Pitch 0.5mm, IPC Medium Density"
  oval 0.8x0.3 smd: 1(-1.6,0.75) 2(-1.6,0.25) 3(-1.6,-0.25) 4(-1.6,-0.75) 5(1.6,-0.75) 6(1.6,-0.25) 7(1.6,0.25) 8(1.6,0.75)
  silkscreen extent -1.05,-1.05 0.38,1.05, body extent -1.56,-1 1.56,1, height 0.9
DGQ0010D-C01-MFG [mm]
  rrect33% 1.45x0.3 smd paste+0 mask+0: 1(-2.2,1) 2(-2.2,0.5) 3(-2.2,0) 4(-2.2,-0.5) 5(-2.2,-1) 6(2.2,-1) 7(2.2,-0.5) 8(2.2,0) 9(2.2,0.5) 10(2.2,1)
  rrect5% 2.2x3.1 smd paste-1000 mask-1000: 11(0,0)
  silkscreen extent -3.6,-1.95 1.55,1.95, body extent -3.03,-1.8 3.03,1.8, height 0.25
DRV0006A [mm] "SON, 6-Leads, Body 2x2mm, Pitch 0.65mm, Thermal Pad 1.6x1mm, TI Recommended"
  rrect33% 0.45x0.3 smd: 1(-0.975,0.65) 2(-0.975,0) 3(-0.975,-0.65) 4(0.975,-0.65) 5(0.975,0) 6(0.975,0.65)
  rrect14% 1x0.7 on Top Paste: 7(0,-0.45) 7(0,0.45)
  rrect10% 1x1.6 smd paste-0.5: 7(0,0)
  silkscreen extent -1.05,-1.2 1.05,1.2, body extent -1.05,-1.05 1.05,1.05, height 0.81
FP-0731375003_CONN_BNC_RCPT-MFG [mm]
  rrect7% 1.39x1.39 hole 0.89 paste-1000 mask+0: 1(0,15.61)
  round 1.39 hole 0.89 paste-1000 mask+0: 2(2.54,15.61)
  round 3.06 hole 2.01 paste-1000 mask+0: 3(-5.08,10.53) 4(5.08,10.53)
  silkscreen extent -7.44,4.35 7.44,18.26, body extent -7.54,-17.75 7.54,17.75, height 0.25
FP-74438335330_SMT2_3MM0_3MM0-MFG [mm]
  rrect8% 1.3x3.4 smd paste+0 mask+0: 1(-1.05,0) 2(1.05,0)
  silkscreen extent 0,-1.6 0,1.6, body extent -1.8,-1.8 1.8,1.8, height 0.25
FP-ACM2012-900-2P-T001_SMD4-MFG [mm]
  rrect25% 0.75x0.4 smd paste+0 mask+0: 1(-0.925,0.4) 2(-0.925,-0.4) 3(0.925,-0.4) 4(0.925,0.4)
  silkscreen extent -2,-0.7 0.18,0.7, body extent -1.4,-0.8 1.4,0.8, height 0.25
FP-CGA4J1X7S1E106K125AC_0805-MFG [mm]
  rrect13% 0.8x1.05 smd paste+0 mask+0: 1(-0.925,0) 2(0.925,0)
  silkscreen extent -0.15,-0.72 0.15,0.72, body extent -1.43,-0.82 1.43,0.82, height 0.25
FP-ERJ-3GEY0R00V_0603-MFG [mm]
  rrect15% 0.65x0.9 smd paste+0 mask+0: 1(-0.725,0) 2(0.725,0)
  silkscreen extent -1.03,-0.87 1.03,0.87, body extent -1.15,-0.58 1.15,0.58, height 0.25
FP-MPIA2510V2-4R7-R_1008-MFG [mm]
  rrect13% 0.8x2.2 smd paste+0 mask+0: 1(-1,0) 2(1,0)
  silkscreen extent -0.23,-1.1 0.23,1.1, body extent -1.5,-1.2 1.5,1.2, height 0.25
FP-PMEG6020ELRX_SOD123W-MFG [mm]
  rrect8% 1.2x1.2 smd paste-1000 mask+0: 1(-1.4,0) 2(1.4,0)
  silkscreen extent -2.85,-0.95 0.43,0.95, body extent -2.2,-1.05 2.2,1.05, height 0.25
FP-TX1-ZB1459-BED_SMT8_8MM1_10MM0-MFG [mm]
  rrect6% 1.7x1.6 smd paste+0 mask+0: 1(-5.4,3) 2(-5.4,1) 3(-5.4,-1) 4(-5.4,-3) 5(5.4,-3) 6(5.4,-1) 7(5.4,1) 8(5.4,3)
  silkscreen extent -5.53,-5 4.1,5, body extent -6.35,-5.1 6.35,5.1, height 0.25
FP-UMK325AB7106KMHP_1210-MFG [mm]
  rrect8% 1.25x2.5 smd paste+0 mask+0: 1(-1.7,0) 2(1.7,0)
  silkscreen extent -0.7,-1.4 0.7,1.4, body extent -2.42,-1.5 2.42,1.5, height 0.25
Harwin_S2751-46R [mm] "Test Point, SMT"
  rect 2.2x1.4 smd: 1(0,0)
  body extent -1,-0.6 1,0.6, height 1.4
HXB_F61 [mm] "SMD, 2-Leads, Dia 6.3mm"
  rect 3.5x1.6 smd: 1(-2.7,0) 2(2.7,0)
  silkscreen extent -3.4,-3.4 3.4,3.4, body extent -3.4,-3.4 3.4,3.4, height 6.11
IEC_HighVoltage_Small [mil]
  silkscreen extent -107,-88 107,97
IEC_HotSurface_Small [mil]
  silkscreen extent -107,-93 107,92
Keystone5005 [mil] "Keystone Compact loops"
  round 87 hole 63: 1(0,0)
  silkscreen extent -70,-70 70,70, body extent -63,-63 62,63, height 225
Keystone5006 [mil] "Keystone Compact loops"
  round 87 hole 63: 1(0,0)
  silkscreen extent -70,-70 70,70, body extent -63,-63 62,63, height 225
Keystone5007 [mil] "Keystone Compact loops"
  round 87 hole 63: 1(0,0)
  silkscreen extent -70,-70 70,70, body extent -63,-63 62,63, height 225
"LS L29K_Red" [mm] "SMD, 2-Leads, Body 1.3x0.8mm"
  rect 0.8x0.8 smd paste-0.4: 1(-0.75,0) 2(0.75,0)
  silkscreen extent -0.1,-0.5 1.45,0.5, body extent -0.9,-0.45 0.9,0.45, height 0.67
Molex_0395443002 [mm] "Terminal Block, 5.08mm, 2x1, TH"
  rect 2.15x2.15 hole 1.65: 1(-2.54,0)
  round 2.15 hole 1.65: 2(2.54,0)
  silkscreen extent -5.4,-4.83 5.08,5.08, body extent -5.08,-4.83 5.08,5.08, height 14.48
RQS0052A-MFG [mm]
  rrect10% 1.05x1.05 smd paste+0 mask+0: 1(-5.675,5.2) 16(-5.675,-5.2) 27(5.675,-5.2) 42(5.675,5.2)
  rrect25% 1.05x0.4 smd paste+0 mask+0: 2(-5.675,4.225) 3(-5.675,3.575) 4(-5.675,2.925) 5(-5.675,2.275) 6(-5.675,1.625) 7(-5.675,0.975) 8(-5.675,0.325) 9(-5.675,-0.325) 10(-5.675,-0.975) 11(-5.675,-1.625) 12(-5.675,-2.275) 13(-5.675,-2.925) 14(-5.675,-3.575) 15(-5.675,-4.225) 28(5.675,-4.225) 29(5.675,-3.575) 30(5.675,-2.925) 31(5.675,-2.275) 32(5.675,-1.625) 33(5.675,-0.975) 34(5.675,-0.325) 35(5.675,0.325) 36(5.675,0.975) 37(5.675,1.625) 38(5.675,2.275) 39(5.675,2.925) 40(5.675,3.575) 41(5.675,4.225)
  rrect25% 0.4x1.05 smd paste+0 mask+0: 17(-1.935,-5.675) 18(-1.285,-5.675) 19(-0.635,-5.675) 20(0.015,-5.675) 21(0.665,-5.675) 22(1.315,-5.675) 23(1.965,-5.675) 24(2.615,-5.675) 25(3.265,-5.675) 26(3.915,-5.675) 43(3.915,5.675) 44(3.265,5.675) 45(2.615,5.675) 46(1.965,5.675) 47(1.315,5.675) 48(0.665,5.675) 49(0.015,5.675) 50(-0.635,5.675) 51(-1.285,5.675) 52(-1.935,5.675)
  silkscreen extent -6.88,-6.05 4.77,6.05, body extent -6,-6 6,6, height 1
SML-E1_Yellow [mm] "SMD, 2-Leads, Body 1.6x0.8mm"
  rect 0.8x0.8 smd: 1(0.825,0) 2(-0.825,0)
  silkscreen extent -1.8,-0.8 1.3,0.8, body extent -0.85,-0.45 0.85,0.45, height 0.46
SNT-100-BK-G [mil] "Samtec STEP model"
  round 1 on Mech3: 0(0,0)
  body extent -100,-50 100,50, height 344
SOD-123 [mm] "On Semi recommended land pattern"
  rect 0.915x1.22 smd: 1(-1.637,0) 2(1.637,0)
  silkscreen extent -2.74,-1.17 2.03,1.17, body extent -1.93,-0.9 1.93,0.9, height 1.35
SOD-323 [mm] "NXP recommended land pattern"
  rect 0.6x0.6 smd paste-0.05: 1(-1.1,0) 2(1.1,0)
  silkscreen extent -2.06,-0.87 1.53,0.86, body extent -1.3,-0.67 1.3,0.68, height 1.1
TEC_282834-2 [mm] "TEC"
  rect 1.6x1.6 hole 1.1: 1(-1.27,0)
  round 1.6 hole 1.1: 2(1.27,0)
  silkscreen extent -3.66,-3.4 2.9,3.4, body extent -2.77,-3.25 2.77,3.25, height 10.01
Testpoint_Keystone_Compact [mil] "Compact SMT test point"
  rrect10% 275x175 smd: 1(0,0)
  silkscreen extent -110,-80 110,80, body extent -75,-56 75,56, height 91
TI_Stacked_Overlay_Small [mil]
  silkscreen extent -418,-98 418,98
TRIM_3224X [mm] "Bourns"
  rect 1.9x1.3 smd: 1(-2.55,1.25) 3(-2.55,-1.25)
  rect 1.9x2 smd: 2(2.55,0)
  silkscreen extent -1.9,-2.5 1.9,2.5, body extent -1.8,-2.4 1.8,2.4, height 5.31
TSW-102-07-G-S [mm] "Samtec 100mil, 1x2, 230 mil above insulator"
  rrect50% 1.65x1.65 hole 1.016: 1(-1.27,0)
  round 1.65 hole 1.016: 2(1.27,0)
  body extent -2.54,-1.27 2.54,1.27, height 8.38
TSW-103-07-G-S [mm] "Samtec 100mil, 1x3, 230 mil above insulator"
  rrect50% 1.65x1.65 hole 1.016: 1(-2.54,0)
  round 1.65 hole 1.016: 2(0,0) 3(2.54,0)
  body extent -3.81,-1.27 3.81,1.27, height 8.38
WEEE_Minimum [mil] "WEEElie bin"
  silkscreen extent -95,-172 99,104

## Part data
15VIN 15VINF: library part CMP-0055142-2, "Test Point, Compact, Red, TH", Color=Red, Manufacturer="Keystone Electronics", Supplier Part Number 1=36-5005-ND
C1 C11: library part CMP-0750154-1, "CAP, CERM, 10 µF, 25 V,+/- 10%, X7R, AEC-Q200 Grade 1, 1206", Cap_Case=1206, Manufacturer="Taiyo Yuden", TempCo=X7R, Tolerance_%=10%, Value2=25V, ValueDisplayed=10µF
C2 C12: library part CMP-0078265-1, "CAP, CERM, 0.22 µF, 16 V,+/- 10%, X7R, AEC-Q200 Grade 1, 0402", Cap_Case=0402, Manufacturer=MuRata, Supplier Part Number 1=490-10671-1-ND, TempCo=X7R, Tolerance_%=10%, Value2=16V, ValueDisplayed=0.22µF
C3 C13: library part CMP-0007975-2, "CAP, CERM, 2.2 uF, 25 V, +/- 10%, X7R, AEC-Q200 Grade 1, 0805", Cap_Case=0805, Manufacturer=TDK, Supplier Part Number 1=445-6965-1-ND, TempCo=X7R, Tolerance_%=10%, Value1=Unknown, Value2=25V, ValueDisplayed=2.2uF
C4: library part CMP-0750159-1, "CAP, AL, 47 µF, 25 V, +/- 20%, 0.05 ohm, AEC-Q200 Grade 1, SMD", Cap_Case=6.3x5.8mm, Manufacturer=Chemi-Con, Tolerance_%=20%, Value1="0.05 ohm", Value2=25V, ValueDisplayed=47µF
C5 C23: library part CMP-0006348-2, "CAP, CERM, 22 pF, 50 V, +/- 5%, C0G/NP0, AEC-Q200 Grade 1, 0402", Cap_Case=0402, Manufacturer=MuRata, Supplier Part Number 1=490-9648-1-ND, TempCo=C0G/NP0, Tolerance_%=5%, Value1=Unknown, Value2=50V, ValueDisplayed=22pF
C6 C14: library part CMP-0006251-2, "CAP, CERM, 68 pF, 50 V, +/- 5%, C0G/NP0, 0402", Alternate Manufacturer=Murata, Alternate PartNumber=GRM1555C1H680JA01D, Cap_Case=0402, Manufacturer=TDK, Supplier Part Number 1=445-1245-1-ND, TempCo=C0G/NP0, Tolerance_%=5%, Value1=Unknown, Value2=50V, ValueDisplayed=68pF
C7: library part CMP-0081062-1, "CAP, CERM, 10 µF, 25 V,+/- 5%, X7R, AEC-Q200 Grade 1, 1206", Cap_Case=1206_180, Manufacturer=Kemet, Supplier Part Number 1=399-15734-1-ND, TempCo=X7R, Tolerance_%=5%, Value2=25V, ValueDisplayed=10µF
C8 C31: library part CMP-0009163-2, "CAP, CERM, 4.7 uF, 50 V, +/- 20%, X7R, AEC-Q200 Grade 1, 1210", Cap_Case=1210, Manufacturer=TDK, Supplier Part Number 1=445-13030-1-ND, TempCo=X7R, Tolerance_%=20%, Value1=Unknown, Value2=50V, ValueDisplayed=4.7uF
C9 C26: library part CMP-0750099-1, "CAP, CERM, 1 µF, 35 V,+/- 10%, X5R, AEC-Q200 Grade 3, 0402", Cap_Case=0402, Manufacturer=MuRata, TempCo=X5R, Tolerance_%=10%, Value2=35V, ValueDisplayed=1µF
C10 C27: library part CMP-0006356-2, "CAP, CERM, 0.1 uF, 50 V, +/- 10%, X7R, AEC-Q200 Grade 1, 0402", Cap_Case=0402, Manufacturer=MuRata, Supplier Part Number 1=490-10672-1-ND, TempCo=X7R, Tolerance_%=10%, Value1=Unknown, Value2=50V, ValueDisplayed=0.1uF
C15 C16 C17 C18: library part CMP-0084048-1, "CAP, CERM, 0.022 µF, 1000 V,+/- 10%, X7R, AEC-Q200 Grade 1, 1206", Cap_Case=1206, Manufacturer=Kemet, TempCo=X7R, Tolerance_%=10%, Value2=1000V, ValueDisplayed=0.022µF
C19 C20 C21 C38: library part CMP-0009326-2, "CAP, CERM, 0.1 uF, 1000 V, +/- 10%, X7R, 1812", Cap_Case=1812, Manufacturer=Kemet, Supplier Part Number 1=399-6523-1-ND, TempCo=X7R, Tolerance_%=10%, Value1=Unknown, Value2=1000V, ValueDisplayed=0.1uF
C22 C28 C32 C35 C47 C53: library part CMP-0079911-1, "CAP, CERM, 0.1 µF, 50 V,+/- 10%, X8R, AEC-Q200 Grade 0, 0603", Cap_Case=0603, Manufacturer=TDK, Supplier Part Number 1=445-173697-1-ND, TempCo=X8R, Tolerance_%=10%, Value2=50V, ValueDisplayed=0.1µF
C24 C25 C33 C34: library part CMP-0091069-1, "Cap Ceramic 10uF 25V X7S 10% Pad SMD 0805 +125°C Automotive T/R", Manufacturer="TDK Corporation", Operating Temperature Range="-55°C to +125°C", TempCo=22%, Temperature Characteristic=X7S, Tolerance_%=0.1%, ValueDisplayed=10uF
C29 C36: library part CMP-0009155-2, "CAP, CERM, 10 uF, 25 V, +/- 20%, X7R, AEC-Q200 Grade 1, 1210", Cap_Case=1210, Manufacturer=TDK, Supplier Part Number 1=445-5720-1-ND, TempCo=X7R, Tolerance_%=20%, Value1=Unknown, Value2=25V, ValueDisplayed=10uF
C30 C37: library part CMP-0007139-4, "CAP, CERM, 1 uF, 25 V, +/- 10%, X7R, AEC-Q200 Grade 1, 0603", Cap_Case=0603, Manufacturer=MuRata, Supplier Part Number 1=490-10673-1-ND, TempCo=X7R, Tolerance_%=10%, Value1=Unknown, Value2=25V, ValueDisplayed=1uF
C39 C40 C56 C57: library part CMP-0860835-1, "CAP, CERM, 43 pF, 50 V,+/- 5%, C0G/NP0, AEC-Q200 Grade 1, 0402", Cap_Case=0402, Manufacturer=MuRata, TempCo=C0G/NP0, Tolerance_%=5%, Value2=50V, ValueDisplayed=43pF
C41 C44: library part CMP-0082523-1, "CAP, CERM, 1 µF, 25 V,+/- 10%, X7R, AEC-Q200 Grade 1, 0603", Cap_Case=0603, Manufacturer=TDK, Supplier Part Number 1=445-9819-1-ND, TempCo=X7R, Tolerance_%=10%, Value2=25V, ValueDisplayed=1µF
C42 C43: library part CMP-0006308-2, "CAP, CERM, 100 pF, 50 V, +/- 5%, C0G/NP0, AEC-Q200 Grade 1, 0402", Cap_Case=0402, Manufacturer=TDK, Supplier Part Number 1=445-5596-1-ND, TempCo=C0G/NP0, Tolerance_%=5%, Value1=Unknown, Value2=50V, ValueDisplayed=100pF
C45 C46 C50 C51 C52 C55: library part CMP-0007214-4, "CAP, CERM, 39 pF, 50 V, +/- 5%, C0G/NP0, 0603", Cap_Case=0603, Manufacturer=MuRata, Supplier Part Number 1=490-1417-1-ND, TempCo=C0G/NP0, Tolerance_%=5%, Value1=Unknown, Value2=50V, ValueDisplayed=39pF
C48: library part CMP-0084059-1, "CAP, CERM, 22 µF, 25 V,+/- 10%, X5R, AEC-Q200 Grade 3, 1210", Cap_Case=1210, Manufacturer=MuRata, TempCo=X5R, Tolerance_%=10%, Value2=25V, ValueDisplayed=22µF
C49: library part CMP-0064919-2, "CAP, CERM, 1 uF, 630 V,+/- 10%, X7R, AEC-Q200 Grade 1, 2220", Cap_Case=2220, Manufacturer="Knowles Capacitors", PartNumber=2220Y6300105KXTWS2, Supplier Part Number 1=1608-1181-1-ND, TempCo=X7R, Tolerance_%=10%, Value1=Unknown, Value2=630V, ValueDisplayed=1uF
C54: library part CMP-0089980-1, "10µF ±10% 50V Ceramic Capacitor X7R 1210 (3225 Metric)", Digikey Part Number=587-6160-1-ND, Manufacturer="Taiyo Yuden", Mouser Part Number=963-UMK325AB7106KMHP, Operating Temperature Range="-55°C to +125°C", TempCo=15%, Temperature Characteristic=X7R, Tolerance_%=10%, ValueDisplayed=10uF
C58 C59 C60 C61: library part CMP-0006483-1, "CAP, CERM, 62 pF, 50 V, +/- 5%, C0G/NP0, 0402", Cap_Case=0402, Manufacturer=MuRata, Supplier Part Number 1=81-GRM1555C1H620JA1D, TempCo=C0G/NP0, Tolerance_%=5%, Value1=Unknown, Value2=50V, ValueDisplayed=62pF
C62 C63: library part CMP-0006289-1, "CAP, CERM, 0.1 uF, 50 V, +/- 10%, X6S, 0402", Cap_Case=0402, Manufacturer=TDK, Supplier Part Number 1=445-7356-1-ND, TempCo=X6S, Tolerance_%=10%, Value1="0.039064 ohm", Value2=50V, ValueDisplayed=0.1uF
D1 D3 D4 D6: library part CMP-0090247-1, "Diode Schottky 60V 2A Surface Mount CFP3", Digikey Part Number=1727-2298-1-ND, Forward Current=2.83A, Manufacturer=Nexperia, Max Surge Forward Current=50A, Mouser Part Number=771-PMEG6020ELRX, Operating Temperature Range="to +175°C", Part Number=PMEG6020ELRX, Peak Reverse Current=0.09uA, ValueDisplayed=110pF
D2 D5: library part CMP-0084402-3, "Diode, Zener, 18 V, 500 mW, AEC-Q101, SOD-123", Manufacturer="Diodes Inc.", Power_W=500mW, Value1=0.5W
D11 D12: library part CMP-0028447-2, "Diode, Schottky, 30 V, 0.2 A, SOD-323", Manufacturer="Diodes Inc.", Value1=0.2A, Value2=1V
GND_LV GNDHV GNDLV GNDLVF ISO15VGND ISO15VSW: library part CMP-0055143-1, "Test Point, Compact, Black, TH", Color=Black, Manufacturer=Keystone, Supplier Part Number 1=36-5006-ND
HS_FLT LDO LS_FLT: library part CMP-0002902-2, "LED, Red, SMD", Color=Red, Manufacturer=OSRAM, Value1=W, Value2=1.8V
HS_OC LS_OC: library part CMP-0002977-1, "LED, Yellow, SMD", Color=yellow, Manufacturer=Rohm, Power_TotalModule=54mW, Supplier Part Number 1=511-1588-1-ND, Value1=0.054W, Value2=2.2V
HVIN ISO15VH ISO15VL LDO5V: library part CMP-0055142-1, "Test Point, Compact, Red, TH", Color=Red, Manufacturer=Keystone, Supplier Part Number 1=36-5005-ND
J1 J4: library part CMP-0095823-1, "Connector BNC Female 0Hz To 2GHz 50 Ohm Solder Right Angle Through Hole Gold Tray", Dielectric Material=Polypropylene, Digikey Part Number=WM5514-ND, Frequency_Fixed=2GHz, Manufacturer=Molex, Mouser Part Number=538-73137-5003, Operating Temperature Range=to, Voltage_V=500V
J2 J3: library part CMP-0075407-2, "Header, 100mil, 3x1, Gold, TH", Color=Black, Current_A=6.3A, Manufacturer=Samtec, Supplier Part Number 1=SAM1029-03-ND, Voltage_V=550V
J5: library part CMP-0055342-2, "Terminal Block, 5.08mm, 2x1, TH", Color=Black, Current_A=15A, Manufacturer=Molex, Supplier Part Number 1=WM7853-ND, Voltage_V=300V
J6: library part CMP-0054974-1, "Terminal Block, 2x1, 2.54mm, TH", Manufacturer="TE Connectivity", Supplier Part Number 1=A98333-ND
J7: library part CMP-0075405-2, "Header, 100mil, 2x1, Gold, TH", Color=Black, Current_A=6.3A, Manufacturer=Samtec, Supplier Part Number 1=SAM1029-02-ND, Voltage_V=550V
L1 L2: library part CMP-0090507-1, "4.7µH Shielded Molded Inductor 1.22A 262mOhm Max 1008 (2520 Metric)", Digikey Part Number=283-4799-1-ND, Manufacturer=Eaton, Mouser Part Number=704-MPIA2510V2-4R7-R, Operating Temperature Range="-40°C to +125°C", Self Resonant Frequency=25MHz, Test Frequency=1MHz, Tolerance_%=20%
L3: library part CMP-0060122-1, "Inductor, Wirewound, Ferrite, 240 nH, 0.85 A, 0.119999 ohm, SMD", Manufacturer=Coilcraft, PartNumber=0603AF-241KRB, Value1="0.119999 ohm", Value2=0.85A, ValueDisplayed=240nH
L4 L5: library part CMP-0090488-1, "2 Line Common Mode Choke Surface Mount 90 Ohms @ 100MHz 400mA DCR 190mOhm", Digikey Part Number=445-15969-1-ND, Impedance At Frequency="90Ω @ 100MHz", Manufacturer=TDK, Mouser Part Number=810-ACM20129002PT001, Operating Temperature Range="-40°C to +105°C"
L6 L7: library part CMP-0094235-1, "33 µH Shielded Molded Inductor 500 mA 1.33Ohm Max 1212 (3030 Metric)", Digikey Part Number=732-4871-1-ND, Manufacturer=Wurth, Mouser Part Number=710-74438335330, Operating Temperature Range="-40°C to +125°C", Self Resonant Frequency=10MHz, Test Frequency=100kHz, Tolerance_%=20%
LOGO1 LOGO3: library part CMP-0074837-1, "IEC 61010-1 Hot Surface Warning"
LOGO2 LOGO4: library part CMP-0074835-1, "IEC 61010-1 High Voltage Warning"
Logo6: library part CMP-0074838-1, "Texas Instrument Corporate Signature"
Logo8: library part CMP-0074769-1
R1 R3: library part CMP-0020443-3, "RES, 0, 5%, 0.333 W, AEC-Q200 Grade 0, 0805", Manufacturer=Vishay-Dale, Power_W=333mW, Supplier Part Number 1=541-0.0TBCT-ND, TempCo="200 ppm/C", Tolerance_%=5%, Value2=0.333W, Value_Code=0000, ValueDisplayed=0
